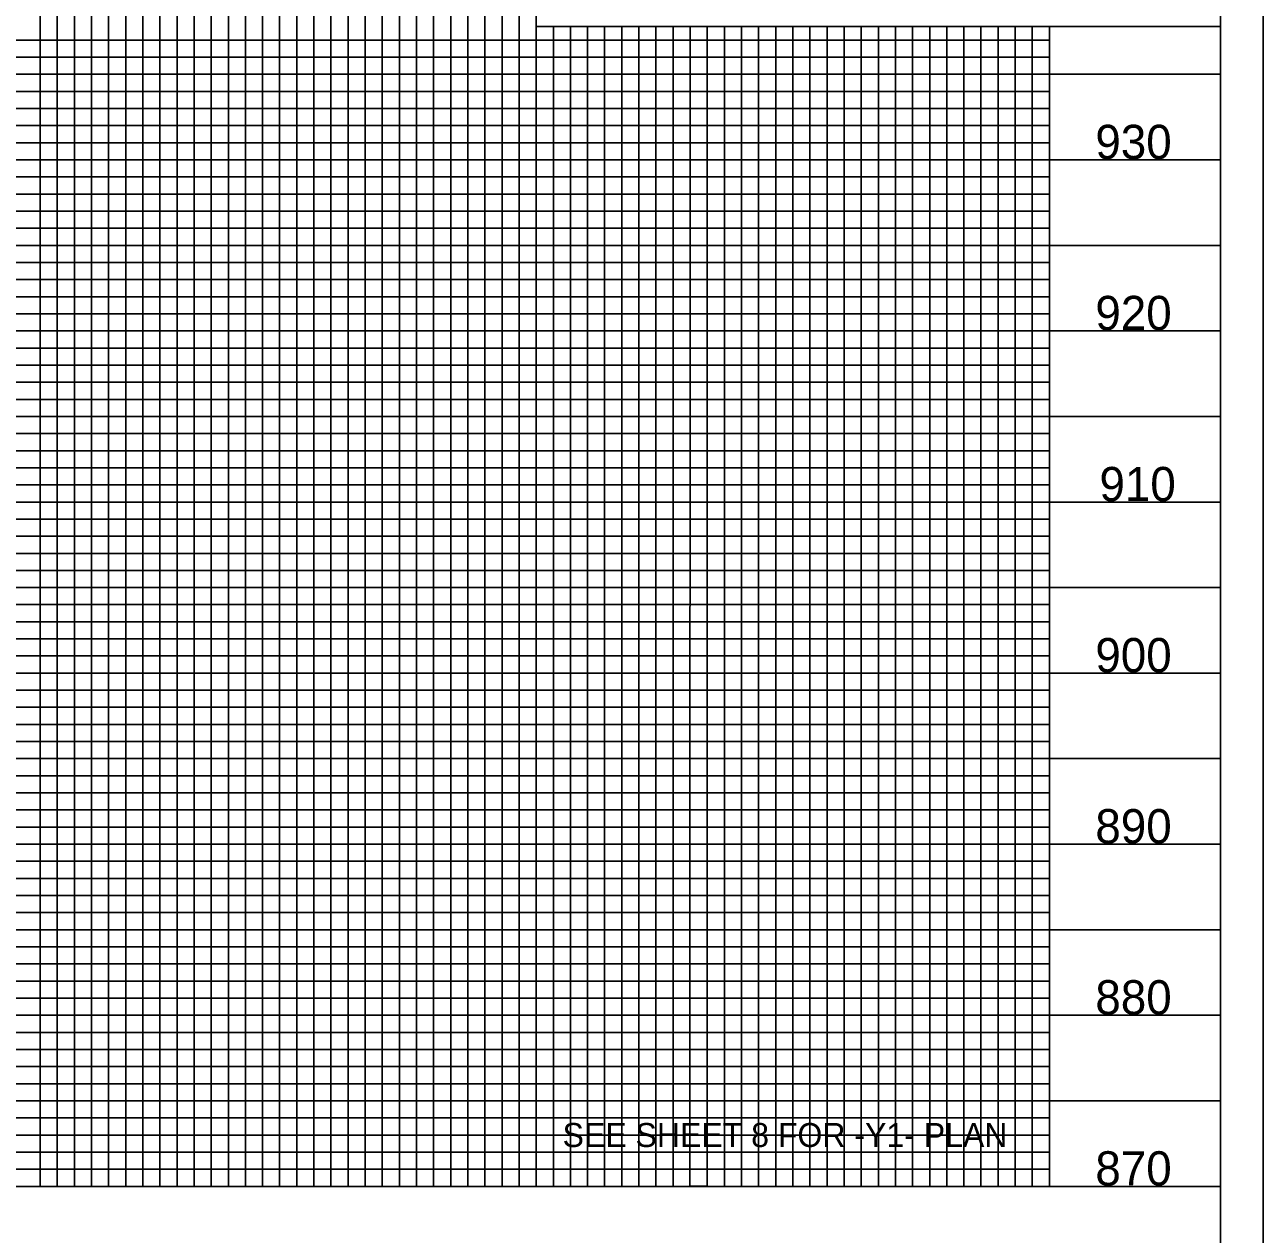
# Model space of a CAD drawing. Extents: x 1650661 to 1652901, y 832691 to 833791.
# Drawn here: x 1652354.8 to 1652716.8, y 833252 to 833605.5 of the extents above; entities that cross this region are included whole.
import ezdxf

# ---------------------------------------------------------------- set-up
doc = ezdxf.new("R2010")
doc.units = 0
for name, color, linetype in [('Exist Vertical Profile Vertical Axis Label', 7, 'Continuous'), ('Prop Dimension', 7, 'Continuous'), ('Prop Grid Mask', 7, 'Continuous'), ('Sheet DOT Grid CELL', 7, 'Continuous'), ('Sheet Plot Border Inside CELL', 7, 'Continuous'), ('Sheet Profile CELL', 7, 'Continuous'), ('Sheet Profile Grid Major CELL', 7, 'Continuous'), ('Sheet Profile Grid Middle CELL', 7, 'Continuous'), ('Sheet Profile Grid Minor CELL', 7, 'Continuous'), ('Sheet Sticker Exception Certification CELL', 7, 'Continuous')]:
    doc.layers.add(name, color=color, linetype=linetype)

msp = doc.modelspace()

# ---------------------------------------------------------------- linework, layer by layer
at = {"layer": 'Prop Grid Mask'}
msp.add_lwpolyline([(1652509.28, 833291.02), (1652509.28, 833271.02), (1652644.28, 833271.02), (1652644.28, 833291.02)], close=True, dxfattribs=at)
at = {"layer": 'Sheet DOT Grid CELL'}
for p, q in [((1652404.28, 833266.02), (1652404.28, 833718.48)), ((1652454.28, 833266.02), (1652454.28, 833718.48)), ((1652504.28, 833266.02), (1652504.28, 833628.47)), ((1652554.28, 833266.02), (1652554.28, 833604.97)), ((1652604.28, 833266.02), (1652604.28, 833604.97)), ((1652654.28, 833266.02), (1652654.28, 833604.97)), ((1652704.28, 833566.02), (1651204.28, 833566.02)), ((1652704.28, 833516.02), (1651204.28, 833516.02)), ((1652704.28, 833466.02), (1651204.28, 833466.02)), ((1652704.28, 833416.02), (1651204.28, 833416.02)), ((1652704.28, 833366.02), (1651204.28, 833366.02)), ((1652704.28, 833316.02), (1651204.28, 833316.02))]:
    msp.add_line(p, q, dxfattribs=at)
at = {"layer": 'Sheet Plot Border Inside CELL'}
msp.add_lwpolyline([(1651050.28, 832713.47), (1652716.78, 832713.47), (1652716.78, 833768.57), (1651050.28, 833768.57)], close=True, dxfattribs=at)
at = {"layer": 'Sheet Profile CELL'}
msp.add_line((1651204.28, 833266.02), (1652704.28, 833266.02), dxfattribs=at)
msp.add_lwpolyline([(1652704.28, 833766.02), (1651204.28, 833766.02), (1651204.28, 832716.02), (1652704.28, 832716.02)], close=True, dxfattribs=at)
at = {"layer": 'Sheet Profile Grid Major CELL'}
for points in [[(1652454.28, 833738.96), (1652454.28, 833266.02), (1652504.28, 833266.02), (1652504.28, 833766.02), (1652530.58, 833766.02)], [(1652354.28, 833266.02), (1652404.28, 833266.02), (1652404.28, 833738.96)], [(1652654.28, 833604.97), (1652654.28, 833266.02), (1652704.28, 833266.02), (1652704.28, 833616.02)], [(1652554.28, 833604.97), (1652554.28, 833266.02), (1652604.28, 833266.02), (1652604.28, 833266.02), (1652604.28, 833604.97)], [(1652704.28, 833566.02), (1651204.28, 833566.02), (1651204.28, 833516.02), (1652704.28, 833516.02)], [(1652704.28, 833466.02), (1651204.28, 833466.02), (1651204.28, 833416.02), (1652704.28, 833416.02)], [(1652704.28, 833366.02), (1651204.28, 833366.02), (1651204.28, 833366.02), (1651204.28, 833316.02), (1652704.28, 833316.02)]]:
    msp.add_lwpolyline(points, dxfattribs=at)
at = {"layer": 'Sheet Profile Grid Middle CELL'}
for points in [[(1652379.28, 833738.96), (1652379.28, 833266.02), (1652429.28, 833266.02), (1652429.28, 833738.96)], [(1652479.28, 833738.96), (1652479.28, 833266.02), (1652529.28, 833266.02), (1652529.28, 833604.97)], [(1652529.28, 833528.82), (1652529.28, 833266.02), (1652579.28, 833266.02), (1652579.28, 833604.97)], [(1652579.28, 833528.82), (1652579.28, 833266.02), (1652629.28, 833266.02), (1652629.28, 833604.97)], [(1652704.28, 833591.02), (1651204.28, 833591.02), (1651204.28, 833541.02), (1652529.28, 833541.02)], [(1652529.28, 833541.02), (1652704.28, 833541.02)], [(1652529.28, 833541.02), (1652704.28, 833541.02)], [(1652704.28, 833491.02), (1651204.28, 833491.02), (1651204.28, 833441.02), (1652704.28, 833441.02)], [(1652704.28, 833391.02), (1651204.28, 833391.02), (1651204.28, 833341.02), (1652704.28, 833341.02)], [(1652704.28, 833291.02), (1651204.28, 833291.02)]]:
    msp.add_lwpolyline(points, dxfattribs=at)
at = {"layer": 'Sheet Profile Grid Minor CELL'}
for p, q in [((1651254.28, 833601.02), (1652654.28, 833601.02)), ((1652654.28, 833581.02), (1651254.28, 833581.02)), ((1651254.28, 833576.02), (1652654.28, 833576.02)), ((1652654.28, 833556.02), (1651254.28, 833556.02)), ((1651254.28, 833551.02), (1652654.28, 833551.02)), ((1652654.28, 833531.02), (1651254.28, 833531.02)), ((1651254.28, 833526.02), (1652654.28, 833526.02)), ((1652654.28, 833521.02), (1651254.28, 833521.02)), ((1651254.28, 833511.02), (1652654.28, 833511.02)), ((1652654.28, 833506.02), (1651254.28, 833506.02)), ((1651254.28, 833501.02), (1652654.28, 833501.02)), ((1652654.28, 833496.02), (1651254.28, 833496.02)), ((1651254.28, 833486.02), (1652654.28, 833486.02)), ((1652654.28, 833481.02), (1651254.28, 833481.02)), ((1651254.28, 833476.02), (1652654.28, 833476.02)), ((1652654.28, 833471.02), (1651254.28, 833471.02)), ((1651254.28, 833461.02), (1652654.28, 833461.02)), ((1652654.28, 833456.02), (1651254.28, 833456.02)), ((1651254.28, 833451.02), (1652654.28, 833451.02)), ((1652654.28, 833446.02), (1651254.28, 833446.02)), ((1651254.28, 833436.02), (1652654.28, 833436.02)), ((1652654.28, 833431.02), (1651254.28, 833431.02)), ((1651254.28, 833426.02), (1652654.28, 833426.02)), ((1652654.28, 833421.02), (1651254.28, 833421.02)), ((1651254.28, 833411.02), (1652654.28, 833411.02)), ((1652654.28, 833406.02), (1651254.28, 833406.02)), ((1651254.28, 833401.02), (1652654.28, 833401.02)), ((1652654.28, 833396.02), (1651254.28, 833396.02)), ((1651254.28, 833386.02), (1652654.28, 833386.02)), ((1652654.28, 833381.02), (1651254.28, 833381.02)), ((1652654.28, 833376.02), (1651254.28, 833376.02)), ((1652654.28, 833371.02), (1651254.28, 833371.02)), ((1651254.28, 833361.02), (1652654.28, 833361.02)), ((1652654.28, 833356.02), (1651254.28, 833356.02)), ((1651254.28, 833351.02), (1652654.28, 833351.02)), ((1652654.28, 833346.02), (1651254.28, 833346.02)), ((1651254.28, 833336.02), (1652654.28, 833336.02)), ((1652654.28, 833331.02), (1651254.28, 833331.02)), ((1651254.28, 833326.02), (1652654.28, 833326.02)), ((1652654.28, 833321.02), (1651254.28, 833321.02)), ((1651254.28, 833311.02), (1652654.28, 833311.02)), ((1652654.28, 833306.02), (1651254.28, 833306.02)), ((1651254.28, 833301.02), (1652654.28, 833301.02)), ((1652654.28, 833296.02), (1651254.28, 833296.02)), ((1651254.28, 833286.02), (1652654.28, 833286.02)), ((1652654.28, 833281.02), (1651254.28, 833281.02)), ((1651254.28, 833276.02), (1652654.28, 833276.02))]:
    msp.add_line(p, q, dxfattribs=at)
for points in [[(1652359.28, 833738.96), (1652359.28, 833266.02), (1652364.28, 833266.02), (1652364.28, 833738.96)], [(1652369.28, 833738.96), (1652369.28, 833266.02), (1652374.28, 833266.02), (1652374.28, 833738.96)], [(1652384.28, 833738.96), (1652384.28, 833266.02), (1652389.28, 833266.02), (1652389.28, 833738.96)], [(1652394.28, 833266.02), (1652399.28, 833266.02), (1652399.28, 833738.96)], [(1652394.28, 833738.96), (1652394.28, 833266.02)], [(1652409.28, 833738.96), (1652409.28, 833266.02), (1652414.28, 833266.02), (1652414.28, 833738.96)], [(1652419.28, 833738.96), (1652419.28, 833266.02), (1652424.28, 833266.02), (1652424.28, 833738.96)], [(1652434.28, 833738.96), (1652434.28, 833266.02), (1652439.28, 833266.02), (1652439.28, 833738.96)], [(1652444.28, 833738.96), (1652444.28, 833266.02), (1652449.28, 833266.02), (1652449.28, 833738.96)], [(1652459.28, 833738.96), (1652459.28, 833266.02), (1652464.28, 833266.02), (1652464.28, 833738.96)], [(1652469.28, 833738.96), (1652469.28, 833266.02), (1652474.28, 833266.02), (1652474.28, 833738.96)], [(1652484.28, 833738.96), (1652484.28, 833266.02), (1652489.28, 833266.02), (1652489.28, 833738.96)], [(1652494.28, 833738.96), (1652494.28, 833266.02), (1652499.28, 833266.02), (1652499.28, 833738.96)], [(1652509.28, 833604.97), (1652509.28, 833266.02), (1652514.28, 833266.02), (1652514.28, 833604.97)], [(1652519.28, 833604.97), (1652519.28, 833266.02), (1652524.28, 833266.02), (1652524.28, 833604.97)], [(1652534.28, 833604.97), (1652534.28, 833266.02), (1652534.28, 833266.02), (1652539.28, 833266.02), (1652544.28, 833266.02), (1652544.28, 833604.97)], [(1652539.28, 833604.97), (1652539.28, 833266.02)], [(1652549.28, 833604.97), (1652549.18, 833266.07), (1652554.18, 833266.07), (1652559.28, 833266.02), (1652559.28, 833604.97)], [(1652559.28, 833528.82), (1652559.28, 833266.02), (1652564.28, 833266.02), (1652564.28, 833604.97)], [(1652569.28, 833604.97), (1652569.28, 833266.02), (1652574.28, 833266.02), (1652574.28, 833604.97)], [(1652584.28, 833604.97), (1652584.28, 833266.02), (1652589.28, 833266.02), (1652589.28, 833604.97)], [(1652594.28, 833604.97), (1652594.28, 833266.02), (1652599.28, 833266.02), (1652599.28, 833604.97)], [(1652609.28, 833604.97), (1652609.28, 833266.02), (1652614.28, 833266.02), (1652614.28, 833604.97)], [(1652619.28, 833604.97), (1652619.28, 833266.02), (1652624.28, 833266.02), (1652624.28, 833604.97)], [(1652634.28, 833604.97), (1652634.28, 833266.02), (1652639.28, 833266.02), (1652639.28, 833604.97)], [(1652644.28, 833604.97), (1652644.28, 833266.02), (1652649.28, 833266.02), (1652649.28, 833604.97)], [(1652654.28, 833596.02), (1651254.28, 833596.02), (1651254.28, 833586.02), (1652654.28, 833586.02)], [(1652654.28, 833571.02), (1651254.28, 833571.02), (1651254.28, 833561.02), (1652654.28, 833561.02)], [(1652654.28, 833546.02), (1651254.28, 833546.02), (1651254.28, 833536.02), (1652654.28, 833536.02)], [(1652654.28, 833271.02), (1651254.28, 833271.02)]]:
    msp.add_lwpolyline(points, dxfattribs=at)
at = {"layer": 'Sheet Sticker Exception Certification CELL'}
for p, q in [((1652504.23, 833604.97), (1652504.23, 833628.47)), ((1652504.23, 833604.97), (1652504.23, 833628.47)), ((1652704.27, 833628.46), (1652704.27, 833604.96)), ((1652704.27, 833628.46), (1652704.27, 833604.96)), ((1652704.27, 833604.97), (1652504.23, 833604.97)), ((1652704.27, 833604.97), (1652504.23, 833604.97))]:
    msp.add_line(p, q, dxfattribs=at)

# ---------------------------------------------------------------- texts
at = {"layer": 'Exist Vertical Profile Vertical Axis Label'}
for s, p in [('930', (1652667.71, 833566.27)), ('920', (1652667.71, 833516.27)), ('910', (1652668.91, 833466.27)), ('900', (1652667.71, 833416.27)), ('890', (1652667.71, 833366.27)), ('880', (1652667.71, 833316.27)), ('870', (1652667.71, 833266.27))]:
    msp.add_text(s, height=10, dxfattribs=at).set_placement(p)
at = {"layer": 'Prop Dimension'}
msp.add_text('SEE SHEET 8 FOR -Y1- PLAN', height=7, dxfattribs=at).set_placement((1652511.97, 833277.52))

doc.saveas('drawing.dxf')
